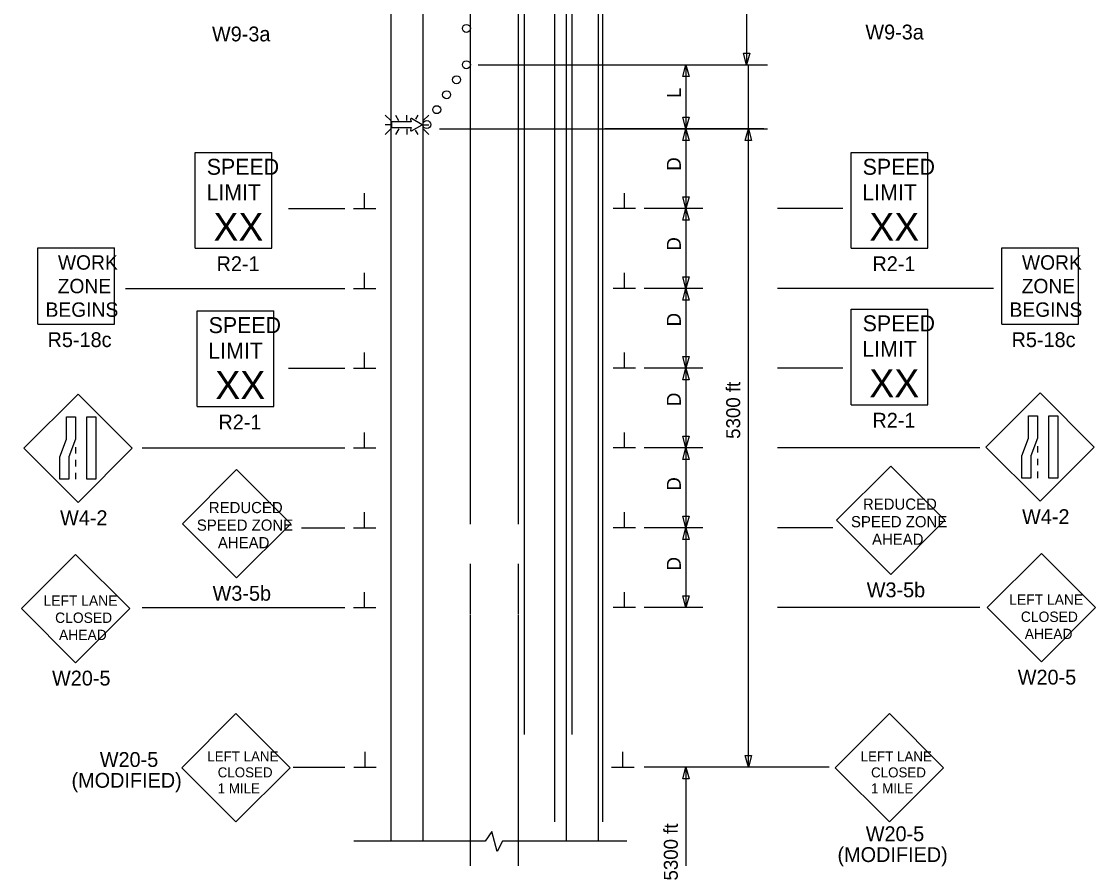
# Model space of a CAD drawing. Extents: x 16729 to 18482, y 7002 to 8333.
# Drawn here: x 16729 to 17267, y 7453 to 7872 of the extents above; entities that cross this region are included whole.
import ezdxf

# ---------------------------------------------------------------- set-up
doc = ezdxf.new("R2010")
doc.units = 0
for name, color, linetype in [('ALI_LEGAL_EX', 7, 'Continuous'), ('PAVT_EDGE_EX', 7, 'Continuous'), ('TRAFFIC_SIGNS_PR', 7, 'Continuous'), ('TYPICAL_TEXT_DIMEN_PR', 7, 'Continuous')]:
    doc.layers.add(name, color=color, linetype=linetype)

msp = doc.modelspace()

# ---------------------------------------------------------------- linework, layer by layer
at = {"layer": 'ALI_LEGAL_EX'}
for p, q in [((16980.68, 8333.08), (16980.68, 7514.94)), ((17004.68, 8333.08), (17004.68, 7514.94)), ((16995.95, 8289.26), (16995.95, 7471.12)), ((17019.95, 8289.26), (17019.95, 7471.12)), ((16953.87, 7620.35), (16953.87, 8241.48)), ((16977.87, 7620.35), (16977.87, 8241.48)), ((16953.87, 7497.94), (16953.87, 7575.09)), ((16977.87, 7497.94), (16977.87, 7575.09)), ((16953.87, 7379.99), (16953.87, 7560.8)), ((16977.87, 7379.99), (16977.87, 7560.8))]:
    msp.add_line(p, q, dxfattribs=at)
for points in [[(16953.87, 7775.35), (16953.87, 7800.35)], [(16977.87, 7775.35), (16977.87, 7800.35)], [(16953.87, 7675.35), (16953.87, 7700.35)], [(16977.87, 7675.35), (16977.87, 7700.35)], [(16953.87, 7575.35), (16953.87, 7600.35)], [(16977.87, 7575.35), (16977.87, 7600.35)], [(16953.87, 7475.35), (16953.87, 7500.35)], [(16977.87, 7475.35), (16977.87, 7500.35)]]:
    msp.add_lwpolyline(points, dxfattribs=at)
at = {"layer": 'PAVT_EDGE_EX'}
for p, q in [((16913.87, 8212.75), (16913.87, 7461.39)), ((16929.87, 8212.75), (16929.87, 7461.39)), ((17001.87, 8212.75), (17001.87, 7461.39)), ((17017.87, 8212.75), (17017.87, 7461.39))]:
    msp.add_line(p, q, dxfattribs=at)
at = {"layer": 'TRAFFIC_SIGNS_PR'}
for p, q in [((16913.89, 7822.57), (16911.06, 7825.39)), ((16916.18, 7825.39), (16917.81, 7822.57)), ((16921.97, 7822.57), (16921.97, 7825.39)), ((16927.44, 7825.39), (16926.23, 7823.3)), ((16932.87, 7825.39), (16930.06, 7822.57)), ((16913.89, 7820.54), (16911.06, 7820.54)), ((16930.06, 7820.54), (16932.87, 7820.54)), ((16913.89, 7818.5), (16911.06, 7815.68)), ((16917.83, 7818.5), (16916.21, 7815.68)), ((16921.97, 7818.5), (16921.97, 7815.68)), ((16926.15, 7817.87), (16927.41, 7815.68)), ((16932.87, 7815.69), (16930.06, 7818.5)), ((16815.84, 7806.57), (16854.24, 7806.57)), ((16815.84, 7758.57), (16815.84, 7806.57)), ((16854.24, 7758.57), (16854.24, 7806.57)), ((17144.69, 7806.57), (17183.09, 7806.57)), ((17144.69, 7758.57), (17144.69, 7806.57)), ((17183.09, 7758.57), (17183.09, 7806.57)), ((16736.98, 7720.5), (16736.98, 7758.9)), ((16736.98, 7758.9), (16775.38, 7758.9)), ((16775.38, 7720.5), (16775.38, 7758.9)), ((16815.84, 7758.57), (16854.24, 7758.57)), ((17144.69, 7758.57), (17183.09, 7758.57)), ((17220.32, 7720.5), (17220.32, 7758.9)), ((17220.32, 7758.9), (17258.72, 7758.9)), ((17258.72, 7720.5), (17258.72, 7758.9)), ((17144.69, 7728.12), (17183.09, 7728.12)), ((17144.69, 7680.12), (17144.69, 7728.12)), ((17183.09, 7680.12), (17183.09, 7728.12)), ((16816.78, 7727.21), (16855.19, 7727.21)), ((16816.78, 7679.21), (16816.78, 7727.21)), ((16855.19, 7679.21), (16855.19, 7727.21)), ((16736.98, 7720.5), (16775.38, 7720.5)), ((17220.32, 7720.5), (17258.72, 7720.5)), ((16757.1, 7685.53), (16729.95, 7658.38)), ((16784.26, 7658.38), (16757.1, 7685.53)), ((17239.44, 7686.09), (17212.29, 7658.94)), ((17266.59, 7658.94), (17239.44, 7686.09)), ((16816.78, 7679.21), (16855.19, 7679.21)), ((17144.69, 7680.12), (17183.09, 7680.12)), ((16729.95, 7658.38), (16757.1, 7631.23)), ((16755.86, 7658.87), (16755.86, 7655.67)), ((16757.1, 7631.23), (16784.26, 7658.38)), ((17212.29, 7658.94), (17239.44, 7631.79)), ((17238.19, 7659.43), (17238.19, 7656.23)), ((17239.44, 7631.79), (17266.59, 7658.94)), ((16755.86, 7652.47), (16755.86, 7649.27)), ((17238.19, 7653.03), (17238.19, 7649.83)), ((16836.59, 7647.68), (16809.43, 7620.52)), ((16863.74, 7620.52), (16836.59, 7647.68)), ((17164.56, 7649.4), (17137.41, 7622.24)), ((17191.71, 7622.24), (17164.56, 7649.4)), ((16755.86, 7646.07), (16755.86, 7642.87)), ((17238.19, 7646.63), (17238.19, 7643.43)), ((16809.43, 7620.52), (16836.59, 7593.37)), ((16836.59, 7593.37), (16863.74, 7620.52)), ((17137.41, 7622.24), (17164.56, 7595.09)), ((17164.56, 7595.09), (17191.71, 7622.24)), ((16755.86, 7605.16), (16728.71, 7578.01)), ((16783.01, 7578.01), (16755.86, 7605.16)), ((17240.07, 7605.64), (17212.92, 7578.49)), ((17267.22, 7578.49), (17240.07, 7605.64)), ((16728.71, 7578.01), (16755.86, 7550.85)), ((16755.86, 7550.85), (16783.01, 7578.01)), ((17212.92, 7578.49), (17240.07, 7551.34)), ((17240.07, 7551.34), (17267.22, 7578.49)), ((16836.26, 7525.37), (16809.11, 7498.22)), ((16863.42, 7498.22), (16836.26, 7525.37)), ((17163.85, 7525.36), (17136.7, 7498.21)), ((17191, 7498.21), (17163.85, 7525.36)), ((16809.11, 7498.22), (16836.26, 7471.07)), ((16836.26, 7471.07), (16863.42, 7498.22)), ((17136.7, 7498.21), (17163.85, 7471.05)), ((17163.85, 7471.05), (17191, 7498.21))]:
    msp.add_line(p, q, dxfattribs=at)
for points in [[(16923.8, 7823.22), (16924.03, 7821.92), (16914.3, 7821.92), (16914.3, 7819.18), (16924.03, 7819.18), (16923.8, 7817.88)], [(16924.3, 7817.52), (16929.61, 7820.54), (16924.3, 7823.58)]]:
    msp.add_lwpolyline(points, dxfattribs=at)
for points in [[(16755.86, 7674.12), (16755.86, 7662.94), (16752.51, 7654.05), (16752.51, 7642.87), (16748.02, 7642.87), (16748.02, 7654.05), (16751.36, 7662.94), (16751.36, 7674.12)], [(16765.99, 7674.12), (16765.99, 7642.87), (16761.5, 7642.87), (16761.5, 7674.12)], [(17238.19, 7674.67), (17238.19, 7663.49), (17234.85, 7654.61), (17234.85, 7643.43), (17230.35, 7643.43), (17230.35, 7654.61), (17233.7, 7663.49), (17233.7, 7674.67)], [(17248.33, 7674.67), (17248.33, 7643.43), (17243.83, 7643.43), (17243.83, 7674.67)]]:
    msp.add_lwpolyline(points, close=True, dxfattribs=at)
for centre in [(16951.8, 7868.82), (16951.8, 7850.6), (16946.83, 7843.09), (16941.87, 7835.59), (16936.9, 7828.08), (16931.93, 7820.58)]:
    msp.add_circle(centre, 2, dxfattribs=at)
for centre, start, end in [((16924.13, 7823.28), 61.4833, 189.9593), ((16924.13, 7817.82), 170.7308, 298.8916)]:
    msp.add_arc(centre, 0.341, start, end, dxfattribs=at)
at = {"layer": 'TYPICAL_TEXT_DIMEN_PR'}
for p, q in [((17092.3, 7968.48), (17092.3, 7850.6)), ((17092.3, 7850.6), (17090.73, 7856.46)), ((17090.73, 7856.46), (17092.3, 7856.46)), ((17092.3, 7856.46), (17093.87, 7856.46)), ((17093.87, 7856.46), (17092.3, 7850.6)), ((16957.62, 7850.6), (17066.87, 7850.6)), ((16957.62, 7850.6), (17102.73, 7850.6)), ((17060.3, 7844.74), (17061.87, 7850.6)), ((17061.87, 7850.6), (17061.87, 7818.5)), ((17061.87, 7850.6), (17063.44, 7844.74)), ((17093.18, 7498.5), (17093.18, 7850.6)), ((17061.87, 7844.74), (17060.3, 7844.74)), ((17063.44, 7844.74), (17061.87, 7844.74)), ((17061.87, 7818.5), (17060.3, 7824.36)), ((17060.3, 7824.36), (17061.87, 7824.36)), ((17061.87, 7824.36), (17063.44, 7824.36)), ((17063.44, 7824.36), (17061.87, 7818.5)), ((16938.26, 7818.5), (17102.73, 7818.5)), ((16957.62, 7818.5), (17066.87, 7818.5)), ((17100.98, 7818.5), (17021.17, 7818.5)), ((17060.3, 7812.64), (17061.87, 7818.5)), ((17061.87, 7818.5), (17061.87, 7778.5)), ((17061.87, 7818.5), (17063.44, 7812.64)), ((17091.62, 7812.64), (17093.19, 7818.5)), ((17093.19, 7818.5), (17094.76, 7812.64)), ((17061.87, 7812.64), (17060.3, 7812.64)), ((17063.44, 7812.64), (17061.87, 7812.64)), ((17093.19, 7812.64), (17091.62, 7812.64)), ((17094.76, 7812.64), (17093.19, 7812.64)), ((16900.74, 7778.5), (16900.74, 7786.28)), ((16900.74, 7778.5), (16900.74, 7786.28)), ((17030.99, 7778.5), (17030.99, 7786.28)), ((17061.87, 7778.5), (17060.3, 7784.36)), ((17060.3, 7784.36), (17061.87, 7784.36)), ((17061.87, 7784.36), (17063.44, 7784.36)), ((17063.44, 7784.36), (17061.87, 7778.5)), ((16862.56, 7778.5), (16890.87, 7778.5)), ((16866.23, 7778.5), (16890.87, 7778.5)), ((16895.12, 7778.5), (16906.37, 7778.5)), ((16895.12, 7778.5), (16906.37, 7778.5)), ((17036.62, 7778.5), (17025.37, 7778.5)), ((17070.41, 7778.5), (17040.87, 7778.5)), ((17060.3, 7772.64), (17061.87, 7778.5)), ((17061.87, 7778.5), (17061.87, 7738.5)), ((17061.87, 7778.5), (17063.44, 7772.64)), ((17140.52, 7778.5), (17107.79, 7778.5)), ((17061.87, 7772.64), (17060.3, 7772.64)), ((17063.44, 7772.64), (17061.87, 7772.64)), ((16900.74, 7738.5), (16900.74, 7746.28)), ((16900.74, 7738.5), (16900.74, 7746.28)), ((17030.99, 7738.5), (17030.99, 7746.28)), ((17061.87, 7738.5), (17060.3, 7744.36)), ((17060.3, 7744.36), (17061.87, 7744.36)), ((17061.87, 7744.36), (17063.44, 7744.36)), ((17063.44, 7744.36), (17061.87, 7738.5)), ((16780.91, 7738.5), (16890.87, 7738.5)), ((16864.87, 7738.5), (16890.87, 7738.5)), ((16895.12, 7738.5), (16906.37, 7738.5)), ((16895.12, 7738.5), (16906.37, 7738.5)), ((17036.62, 7738.5), (17025.37, 7738.5)), ((17070.41, 7738.5), (17040.87, 7738.5)), ((17060.3, 7732.64), (17061.87, 7738.5)), ((17061.87, 7738.5), (17061.87, 7698.5)), ((17061.87, 7738.5), (17063.44, 7732.64)), ((17216.02, 7738.5), (17107.79, 7738.5)), ((17061.87, 7732.64), (17060.3, 7732.64)), ((17063.44, 7732.64), (17061.87, 7732.64)), ((16900.74, 7698.5), (16900.74, 7706.28)), ((16900.74, 7698.5), (16900.74, 7706.28)), ((17030.99, 7698.5), (17030.99, 7706.28)), ((17061.87, 7698.5), (17060.3, 7704.36)), ((17060.3, 7704.36), (17061.87, 7704.36)), ((17061.87, 7704.36), (17063.44, 7704.36)), ((17063.44, 7704.36), (17061.87, 7698.5)), ((16862.56, 7698.5), (16890.87, 7698.5)), ((16878.29, 7698.5), (16890.87, 7698.5)), ((16895.12, 7698.5), (16906.37, 7698.5)), ((16895.12, 7698.5), (16906.37, 7698.5)), ((17036.62, 7698.5), (17025.37, 7698.5)), ((17070.41, 7698.5), (17040.87, 7698.5)), ((17060.3, 7692.64), (17061.87, 7698.5)), ((17061.87, 7698.5), (17063.44, 7692.64)), ((17061.87, 7698.5), (17061.87, 7658.5)), ((17140.52, 7698.5), (17107.79, 7698.5)), ((17061.87, 7692.64), (17060.3, 7692.64)), ((17063.44, 7692.64), (17061.87, 7692.64)), ((16900.74, 7658.5), (16900.74, 7666.28)), ((16900.74, 7658.5), (16900.74, 7666.28)), ((17030.99, 7658.5), (17030.99, 7666.28)), ((17061.87, 7658.5), (17060.3, 7664.36)), ((17060.3, 7664.36), (17061.87, 7664.36)), ((17061.87, 7664.36), (17063.44, 7664.36)), ((17063.44, 7664.36), (17061.87, 7658.5)), ((16789.14, 7658.5), (16890.87, 7658.5)), ((16864.87, 7658.5), (16890.87, 7658.5)), ((16895.12, 7658.5), (16906.37, 7658.5)), ((16895.12, 7658.5), (16906.37, 7658.5)), ((17036.62, 7658.5), (17025.37, 7658.5)), ((17070.41, 7658.5), (17040.87, 7658.5)), ((17060.3, 7652.64), (17061.87, 7658.5)), ((17061.87, 7658.5), (17061.87, 7618.5)), ((17061.87, 7658.5), (17063.44, 7652.64)), ((17209.17, 7658.5), (17107.79, 7658.5)), ((17061.87, 7652.64), (17060.3, 7652.64)), ((17063.44, 7652.64), (17061.87, 7652.64)), ((16900.74, 7618.5), (16900.74, 7626.28)), ((17030.99, 7618.5), (17030.99, 7626.28)), ((17061.87, 7618.5), (17060.3, 7624.36)), ((17060.3, 7624.36), (17061.87, 7624.36)), ((17061.87, 7624.36), (17063.44, 7624.36)), ((17063.44, 7624.36), (17061.87, 7618.5)), ((16869.09, 7618.5), (16890.87, 7618.5)), ((16895.12, 7618.5), (16906.37, 7618.5)), ((17036.62, 7618.5), (17025.37, 7618.5)), ((17070.41, 7618.5), (17040.87, 7618.5)), ((17060.3, 7612.64), (17061.87, 7618.5)), ((17061.87, 7618.5), (17061.87, 7578.5)), ((17061.87, 7618.5), (17063.44, 7612.64)), ((17135.49, 7618.5), (17107.79, 7618.5)), ((17061.87, 7612.64), (17060.3, 7612.64)), ((17063.44, 7612.64), (17061.87, 7612.64)), ((16900.74, 7578.5), (16900.74, 7586.28)), ((17030.99, 7578.5), (17030.99, 7586.28)), ((17061.87, 7578.5), (17060.3, 7584.36)), ((17060.3, 7584.36), (17061.87, 7584.36)), ((17061.87, 7584.36), (17063.44, 7584.36)), ((17063.44, 7584.36), (17061.87, 7578.5)), ((16789.14, 7578.5), (16890.87, 7578.5)), ((16895.12, 7578.5), (16906.37, 7578.5)), ((17036.62, 7578.5), (17025.37, 7578.5)), ((17070.41, 7578.5), (17040.87, 7578.5)), ((17209.17, 7578.5), (17107.79, 7578.5)), ((16900.96, 7498.39), (16900.96, 7506.18)), ((17030.24, 7498.39), (17030.24, 7506.18)), ((17093.19, 7498.5), (17091.62, 7504.36)), ((17091.62, 7504.36), (17093.19, 7504.36)), ((17093.19, 7504.36), (17094.76, 7504.36)), ((17094.76, 7504.36), (17093.19, 7498.5)), ((16864.96, 7498.5), (16890.87, 7498.5)), ((16906.59, 7498.39), (16895.34, 7498.39)), ((17035.87, 7498.39), (17024.62, 7498.39)), ((17133.67, 7498.5), (17040.87, 7498.5)), ((17060.3, 7492.64), (17061.87, 7498.5)), ((17061.87, 7498.5), (17061.87, 7416.94)), ((17061.87, 7498.5), (17063.44, 7492.64)), ((17061.87, 7492.64), (17060.3, 7492.64)), ((17063.44, 7492.64), (17061.87, 7492.64)), ((16964.47, 7466.19), (16961.21, 7461.39)), ((16967.21, 7456.25), (16964.47, 7466.19)), ((16961.21, 7461.39), (16895.27, 7461.39)), ((16969.95, 7461.39), (16967.21, 7456.25)), ((17032.29, 7461.39), (16969.95, 7461.39))]:
    msp.add_line(p, q, dxfattribs=at)

# ---------------------------------------------------------------- texts
at = {"layer": 'TRAFFIC_SIGNS_PR'}
for s, height, p in [('W9-3a', 7.44, (16824.23, 7862.3)), ('W9-3a', 7.44, (17151.83, 7863.27)), ('SPEED', 8, (16821.61, 7795.44)), ('SPEED', 8, (17150.46, 7795.44)), ('LIMIT', 8, (16821.45, 7782.64)), ('LIMIT', 8, (17150.3, 7782.64)), ('XX', 14.031, (16824.96, 7762.33)), ('XX', 14.031, (17153.8, 7762.33)), ('WORK', 7.217, (16746.98, 7747.87)), ('R2-1', 7.44, (16826.52, 7747.13)), ('R2-1', 7.44, (17155.37, 7747.13)), ('WORK', 7.217, (17230.32, 7747.87)), ('ZONE', 7.217, (16746.86, 7736.06)), ('ZONE', 7.217, (17230.2, 7736.06)), ('BEGINS', 7.217, (16740.79, 7724.25)), ('BEGINS', 7.217, (17224.13, 7724.25)), ('SPEED', 8, (16822.55, 7716.08)), ('SPEED', 8, (17150.46, 7716.99)), ('R5-18c', 7.44, (16741.79, 7709.06)), ('LIMIT', 8, (17150.3, 7704.19)), ('R5-18c', 7.44, (17225.13, 7709.06)), ('LIMIT', 8, (16822.39, 7703.28)), ('XX', 14.031, (16825.9, 7682.97)), ('XX', 14.031, (17153.8, 7683.88)), ('R2-1', 7.44, (16827.46, 7667.78)), ('R2-1', 7.44, (17155.37, 7668.68)), ('REDUCED', 5.6, (16822.64, 7625.83)), ('REDUCED', 5.6, (17150.62, 7627.55)), ('W4-2', 7.44, (16748.06, 7619.79)), ('W4-2', 7.44, (17230.4, 7620.35)), ('SPEED ZONE', 5.6, (16816.64, 7617.03)), ('SPEED ZONE', 5.6, (17144.61, 7618.75)), ('AHEAD', 5.6, (17155.17, 7609.95)), ('AHEAD', 5.6, (16827.2, 7608.23)), ('W3-5b', 7.44, (16824.54, 7581.93)), ('W3-5b', 7.44, (17152.51, 7583.65)), ('LEFT LANE', 5.2, (16739.74, 7579.4)), ('LEFT LANE', 5.2, (17223.95, 7579.89)), ('CLOSED', 5.2, (16745.57, 7570.8)), ('CLOSED', 5.2, (17229.78, 7571.29)), ('AHEAD', 5.2, (16747.52, 7562.2)), ('AHEAD', 5.2, (17231.73, 7562.69)), ('W20-5', 7.44, (16744.03, 7539.42)), ('W20-5', 7.44, (17228.24, 7539.9)), ('W20-5', 7.44, (16767.98, 7498.61)), ('LEFT LANE', 5, (16821.89, 7501.38)), ('LEFT LANE', 5, (17149.48, 7501.36)), ('CLOSED', 5, (16827.1, 7493.38)), ('CLOSED', 5, (17154.69, 7493.36)), ('(MODIFIED)', 7.44, (16753.8, 7488.17)), ('1 MILE', 5, (16827.09, 7485.38)), ('1 MILE', 5, (17154.68, 7485.36)), ('W20-5', 7.44, (17152.03, 7461.39)), ('(MODIFIED)', 7.44, (17137.85, 7450.95))]:
    msp.add_text(s, height=height, dxfattribs=at).set_placement(p)
at = {"layer": 'TYPICAL_TEXT_DIMEN_PR'}
for s, p in [('L', (17059.31, 7833.91)), ('D', (17059.31, 7797.46)), ('D', (17059.31, 7757.4)), ('D', (17059.31, 7719.42)), ('5300 ft', (17089.06, 7663.07)), ('D', (17059.31, 7679.47)), ('D', (17059.31, 7637.09)), ('D', (17059.31, 7597.09)), ('5300 ft', (17057.78, 7441.66))]:
    msp.add_text(s, height=7, rotation=90, dxfattribs=at).set_placement(p)

doc.saveas('drawing.dxf')
